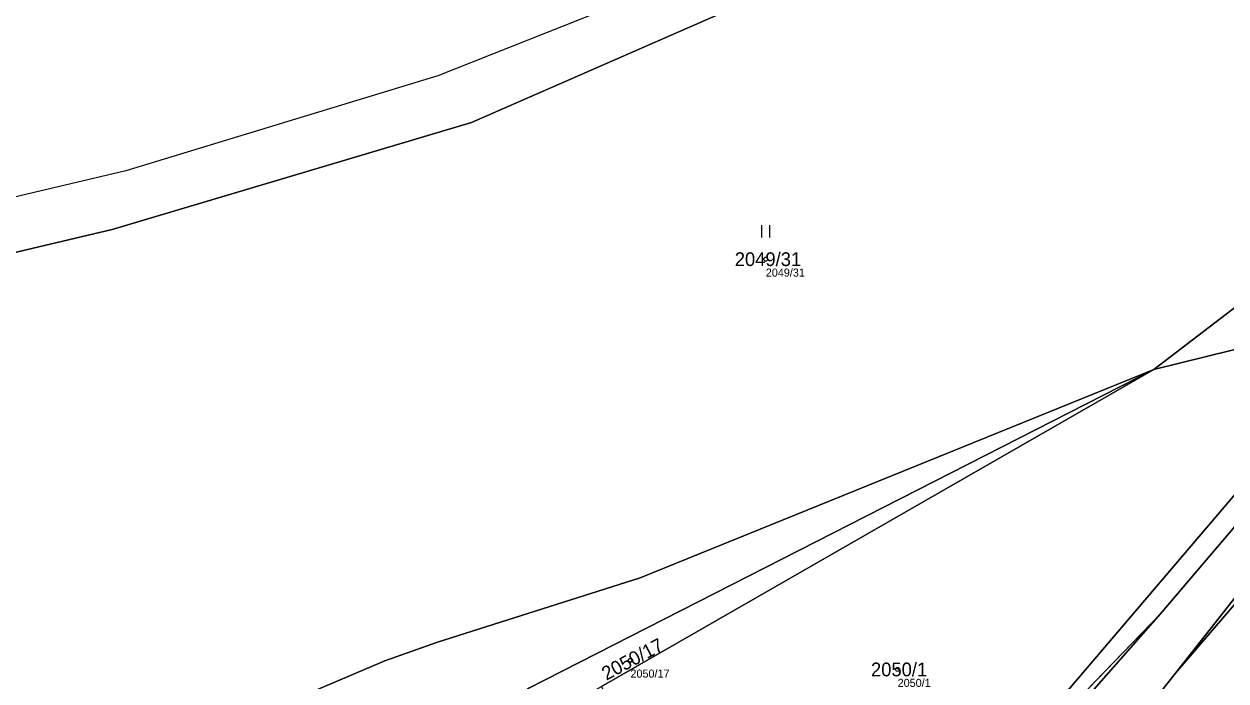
# Model space of a CAD drawing. Extents: x -754731 to -751381, y -1060564 to -1058101.
# Drawn here: x -753725 to -753576.2, y -1058945.8 to -1058864.5 of the extents above; entities that cross this region are included whole.
import ezdxf

# ---------------------------------------------------------------- set-up
doc = ezdxf.new("R2010")
doc.units = 0
for name, color, linetype in [('Definiční body', 7, 'Continuous'), ('Hranice parcel', 7, 'Continuous'), ('Parcelní čísla', 7, 'Continuous'), ('Polygon parcely', 7, 'Continuous'), ('Vnitřní kresba', 7, 'Continuous'), ('Značky kultur', 7, 'Continuous')]:
    doc.layers.add(name, color=color, linetype=linetype)

msp = doc.modelspace()

# ---------------------------------------------------------------- linework, layer by layer
at = {"layer": 'Definiční body'}
for centre in [(-753633.14, -1058893.61), (-753649.89, -1058943.25), (-753616.82, -1058944.4)]:
    msp.add_circle(centre, 0.25, dxfattribs=at)
at = {"layer": 'Hranice parcel'}
for p, q in [((-753613.18, -1058967.44), (-753555.7, -1058900.02)), ((-753555.7, -1058900.02), (-753585.1, -1058907.27)), ((-753585.1, -1058907.27), (-753653.48, -1058946.5)), ((-753613.18, -1058967.44), (-753584.34, -1058937.55)), ((-753582.44, -1058944.85), (-753628.8, -1059003.71))]:
    msp.add_line(p, q, dxfattribs=at)
for points in [[(-753774.44, -1058904.22), (-753714.03, -1058889.94), (-753669.57, -1058876.68), (-753633.34, -1058860.82), (-753608.31, -1058849.02), (-753582.87, -1058835.82), (-753575.81, -1058831.15)], [(-753522.17, -1058860.79), (-753550.69, -1058880.95), (-753585.1, -1058907.27)], [(-753514.44, -1058865.23), (-753544.54, -1058900.8), (-753582.44, -1058944.85)], [(-753514.44, -1058865.23), (-753528.64, -1058876.56), (-753582.44, -1058944.85)], [(-753584.34, -1058937.55), (-753566.08, -1058916.15), (-753552.64, -1058899.85)], [(-753585.1, -1058907.27), (-753648.71, -1058933.06), (-753673.79, -1058941.03), (-753680.28, -1058943.35), (-753696.39, -1058950.19)], [(-753690.64, -1058967.46), (-753662.46, -1058946.7), (-753585.1, -1058907.27)], [(-753638.16, -1059001.49), (-753609.56, -1058966.22), (-753584.34, -1058937.55)]]:
    msp.add_lwpolyline(points, dxfattribs=at)
at = {"layer": 'Polygon parcely'}
for points in [[(-753947.66, -1058906.33), (-753929.25, -1058908.57), (-753925.07, -1058911.95), (-753871.02, -1058913.48), (-753868.46, -1058908.38), (-753801.08, -1058905.36), (-753796.75, -1058905.17), (-753795.34, -1058903.81), (-753784.09, -1058899.13), (-753781.5, -1058896.27), (-753773, -1058895.04), (-753781.44, -1058904.52), (-753774.44, -1058904.22), (-753714.03, -1058889.94), (-753669.57, -1058876.68), (-753633.34, -1058860.82), (-753608.31, -1058849.02), (-753582.87, -1058835.82), (-753575.81, -1058831.15), (-753512.59, -1058789.31), (-753453.73, -1058744.82)], [(-753575.81, -1058831.15), (-753582.87, -1058835.82), (-753608.31, -1058849.02), (-753633.34, -1058860.82), (-753669.57, -1058876.68), (-753714.03, -1058889.94), (-753774.44, -1058904.22)], [(-753566.08, -1058916.15), (-753584.34, -1058937.55), (-753609.56, -1058966.22), (-753638.16, -1059001.49), (-753632.5, -1059003.3), (-753629.99, -1059005.51), (-753628.8, -1059003.71), (-753582.44, -1058944.85), (-753528.64, -1058876.56)], [(-753737.34, -1058970.84), (-753710.65, -1058957.1), (-753702.02, -1058952.58), (-753696.39, -1058950.19), (-753680.28, -1058943.35), (-753673.79, -1058941.03), (-753648.71, -1058933.06), (-753585.1, -1058907.27), (-753550.69, -1058880.95)]]:
    msp.add_lwpolyline(points, dxfattribs=at)
for points in [[(-753544.54, -1058900.8), (-753582.44, -1058944.85), (-753628.8, -1059003.71), (-753564.4, -1058970.95), (-753564.13, -1058967.96), (-753466.68, -1058915.9), (-753470.46, -1058908.58), (-753425.79, -1058886.47), (-753422.05, -1058883.91), (-753416.75, -1058881.74), (-753394.58, -1058873.71), (-753396.75, -1058856.07), (-753400.93, -1058840.72), (-753404.94, -1058826.05), (-753409.99, -1058805.22), (-753404.2, -1058803.88), (-753404.47, -1058802.73), (-753408.42, -1058787.29), (-753504.51, -1058857.3), (-753514.44, -1058865.23)], [(-753522.17, -1058860.79), (-753550.69, -1058880.95), (-753585.1, -1058907.27), (-753555.7, -1058900.02)], [(-753514.44, -1058865.23), (-753528.64, -1058876.56), (-753582.44, -1058944.85), (-753544.54, -1058900.8)], [(-753585.1, -1058907.27), (-753653.48, -1058946.5), (-753647.93, -1058958.94), (-753641.34, -1058973.72), (-753633.6, -1058991.2), (-753632.47, -1058993.74), (-753613.18, -1058967.44), (-753555.7, -1058900.02)], [(-753552.64, -1058899.85), (-753555.7, -1058900.02), (-753613.18, -1058967.44), (-753584.34, -1058937.55), (-753566.08, -1058916.15)], [(-753585.1, -1058907.27), (-753648.71, -1058933.06), (-753673.79, -1058941.03), (-753680.28, -1058943.35), (-753696.39, -1058950.19), (-753690.64, -1058967.46), (-753662.46, -1058946.7)], [(-753678.9, -1058961.08), (-753669.34, -1058955.32), (-753667.73, -1058954.35), (-753665.22, -1058953.11), (-753653.48, -1058946.5), (-753585.1, -1058907.27), (-753662.46, -1058946.7), (-753690.64, -1058967.46)], [(-753609.56, -1058966.22), (-753584.34, -1058937.55), (-753613.18, -1058967.44), (-753632.47, -1058993.74), (-753638.16, -1059001.49)]]:
    msp.add_lwpolyline(points, close=True, dxfattribs=at)
at = {"layer": 'Vnitřní kresba'}
for p, q in [((-753642.12, -1058858.34), (-753673.74, -1058870.93)), ((-753673.74, -1058870.93), (-753712.37, -1058882.69)), ((-753712.37, -1058882.69), (-753745.52, -1058890.48))]:
    msp.add_line(p, q, dxfattribs=at)
at = {"layer": 'Značky kultur'}
for p, q in [((-753633.65, -1058890.91), (-753633.65, -1058889.41)), ((-753632.65, -1058890.91), (-753632.65, -1058889.41))]:
    msp.add_line(p, q, dxfattribs=at)

# ---------------------------------------------------------------- texts
at = {"layer": 'Definiční body'}
for s, p in [('2049/31', (-753633.14, -1058895.77)), ('2050/17', (-753649.89, -1058945.41)), ('2050/1', (-753616.82, -1058946.56))]:
    msp.add_text(s, height=1, dxfattribs=at).set_placement(p)
at = {"layer": 'Parcelní čísla'}
for s, p in [('2049/31', (-753636.98, -1058894.46)), ('2050/1', (-753620.12, -1058945.25))]:
    msp.add_text(s, height=1.7, dxfattribs=at).set_placement(p)
msp.add_text('2050/17', height=1.7, rotation=28, dxfattribs=at).set_placement((-753652.88, -1058945.8))

doc.saveas('drawing.dxf')
